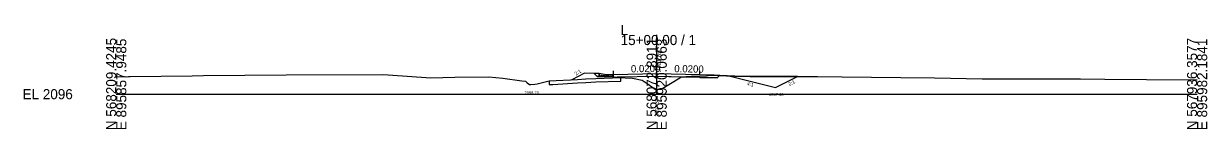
# Model space of a CAD drawing. Extents: x -26 to 1603, y -10 to 13527.
# Drawn here: x -25.7 to 302.8, y 2490.3 to 2519.2 of the extents above; entities that cross this region are included whole.
import ezdxf

# ---------------------------------------------------------------- set-up
doc = ezdxf.new("R2010")
doc.units = 0
for name, color, linetype in [('Default', 7, 'Continuous'), ('Exist XS Center Line Elevation Label', 7, 'Continuous'), ('Exist XS Ground Line', 7, 'Continuous'), ('Old_Level_61', 7, 'Continuous'), ('Old_Level_63', 7, 'Continuous'), ('Prop XS Ditch Slope Text', 7, 'Continuous'), ('Prop XS Ditch Standard Text', 7, 'Continuous'), ('Prop XS Earthwork Shape', 7, 'Continuous'), ('Prop XS EOT Tick Mark', 7, 'Continuous'), ('Prop XS Finish Grade', 7, 'Continuous'), ('Prop XS Finish Grade Earthwork', 7, 'Continuous'), ('Prop XS Finish Grade Paved Shoulder', 7, 'Continuous'), ('Prop XS Finish Grade Pavement', 7, 'Continuous'), ('Prop XS Side Slope Text', 7, 'Continuous'), ('Prop XS Subgrade Earthwork', 7, 'Continuous'), ('Prop XSC Text', 7, 'Continuous'), ('Typical Curb CELL', 7, 'Continuous')]:
    doc.layers.add(name, color=color, linetype=linetype)

msp = doc.modelspace()

# ---------------------------------------------------------------- linework, layer by layer
at = {"layer": 'Exist XS Ground Line'}
for p, q in [((0, 2504.85), (3.43, 2504.91)), ((3.43, 2504.91), (3.9, 2504.92)), ((3.9, 2504.92), (21.1, 2505.11)), ((21.1, 2505.11), (24.21, 2505.16)), ((24.21, 2505.16), (47.12, 2505.33)), ((47.12, 2505.33), (74.04, 2505.47)), ((74.04, 2505.47), (75.48, 2505.36)), ((75.48, 2505.36), (87.36, 2504.55)), ((87.36, 2504.55), (93.95, 2504.71)), ((93.95, 2504.71), (103.4, 2504.84)), ((103.4, 2504.84), (107.28, 2504.4)), ((107.28, 2504.4), (112.54, 2503.72)), ((112.54, 2503.72), (113.57, 2503.61)), ((113.57, 2503.61), (114.01, 2503.16)), ((116.82, 2502.88), (120.13, 2503.66)), ((120.13, 2503.66), (127.98, 2504.11)), ((127.98, 2504.11), (130.32, 2504.27)), ((130.32, 2504.27), (133.16, 2504.39)), ((133.16, 2504.39), (140.03, 2504.6)), ((140.03, 2504.6), (141.25, 2504.53)), ((141.25, 2504.53), (143.26, 2504.48)), ((143.26, 2504.48), (143.77, 2504.37)), ((143.77, 2504.37), (146.01, 2503.86)), ((146.01, 2503.86), (147.61, 2502.8)), ((151.21, 2501.39), (156.43, 2504.56)), ((156.43, 2504.56), (156.8, 2504.79)), ((156.8, 2504.79), (159.53, 2504.98)), ((159.53, 2504.98), (160.92, 2505.03)), ((160.92, 2505.03), (161.97, 2504.98)), ((161.97, 2504.98), (163.86, 2505.13)), ((163.86, 2505.13), (164.75, 2505.23)), ((164.75, 2505.23), (171.69, 2505.02)), ((171.69, 2505.02), (175.91, 2504.88)), ((175.91, 2504.88), (182.67, 2504.86)), ((182.67, 2504.86), (183.98, 2504.87)), ((183.98, 2504.87), (184.77, 2504.87)), ((184.77, 2504.87), (194.62, 2504.93)), ((194.62, 2504.93), (201.45, 2504.84)), ((201.45, 2504.84), (209.66, 2504.7)), ((209.66, 2504.7), (217.79, 2504.6)), ((217.79, 2504.6), (227.12, 2504.5)), ((227.12, 2504.5), (240.35, 2504.29)), ((240.35, 2504.29), (247.3, 2504.3)), ((247.3, 2504.3), (252.3, 2504.3)), ((252.3, 2504.3), (267.61, 2504.21)), ((267.61, 2504.21), (274.36, 2504.14)), ((274.36, 2504.14), (285.92, 2504.07)), ((285.92, 2504.07), (300, 2503.94)), ((114.01, 2503.16), (114.67, 2502.71)), ((114.67, 2502.71), (115.04, 2502.7)), ((115.04, 2502.7), (116.23, 2502.76)), ((116.23, 2502.76), (116.82, 2502.88)), ((147.61, 2502.8), (149.65, 2501.31)), ((149.65, 2501.31), (150.05, 2501.31)), ((150.05, 2501.31), (151.21, 2501.39))]:
    msp.add_line(p, q, dxfattribs=at)
at = {"layer": 'Old_Level_61'}
for p, q in [((120.13, 2503.66), (120.13, 2502.66)), ((133.16, 2503.39), (140.03, 2503.6)), ((140.03, 2503.6), (140.03, 2504.6)), ((120.13, 2502.66), (121.15, 2502.72)), ((121.15, 2502.72), (127.98, 2503.11)), ((127.98, 2503.11), (130.32, 2503.27)), ((130.32, 2503.27), (133.16, 2503.39))]:
    msp.add_line(p, q, dxfattribs=at)
at = {"layer": 'Old_Level_63'}
for p, q in [((150, 2500), (150, 2516.42)), ((0, 2500), (150, 2500)), ((150, 2500), (300, 2500))]:
    msp.add_line(p, q, dxfattribs=at)
at = {"layer": 'Prop XS Earthwork Shape'}
for points in [[(139, 2504.68), (138, 2504.66), (138, 2504.87), (134, 2504.87), (133.5, 2504.86), (132.63, 2505.73), (130, 2505.78), (126.48, 2504.02), (127.98, 2504.11), (130.32, 2504.27), (133.16, 2504.39), (140.03, 2504.6), (141.25, 2504.53), (143.26, 2504.48), (143.77, 2504.37), (146.01, 2503.86), (147.61, 2502.8), (149.65, 2501.31), (150.05, 2501.31), (151.21, 2501.39), (156.43, 2504.56), (156.75, 2504.76), (150, 2504.9)], [(156.75, 2504.76), (156.8, 2504.79), (159.53, 2504.98), (160.92, 2505.03), (161.97, 2504.98), (163.86, 2505.13), (164.75, 2505.23), (167.4, 2505.15), (166.81, 2504.56), (162, 2504.66)], [(167.4, 2505.15), (167.5, 2505.25), (169.53, 2505.09)], [(169.53, 2505.09), (170, 2505.05), (182.96, 2501.81), (189.13, 2504.9), (184.77, 2504.87), (183.98, 2504.87), (182.67, 2504.86), (175.91, 2504.88), (171.69, 2505.02)]]:
    msp.add_lwpolyline(points, close=True, dxfattribs=at)
at = {"layer": 'Prop XS EOT Tick Mark'}
for p, q in [((138, 2505.45), (138, 2506.45)), ((162, 2505.45), (162, 2506.45))]:
    msp.add_line(p, q, dxfattribs=at)
at = {"layer": 'Prop XS Finish Grade'}
for p, q in [((134, 2505.7), (132.63, 2505.73)), ((166, 2505.37), (167.5, 2505.25))]:
    msp.add_line(p, q, dxfattribs=at)
at = {"layer": 'Prop XS Finish Grade Earthwork'}
for p, q in [((130, 2505.78), (126.48, 2504.02)), ((132.63, 2505.73), (130, 2505.78)), ((167.5, 2505.25), (170, 2505.05)), ((170, 2505.05), (182.96, 2501.81)), ((182.96, 2501.81), (189.13, 2504.9))]:
    msp.add_line(p, q, dxfattribs=at)
at = {"layer": 'Prop XS Finish Grade Paved Shoulder'}
msp.add_line((162, 2505.45), (166, 2505.37), dxfattribs=at)
at = {"layer": 'Prop XS Finish Grade Pavement'}
for p, q in [((138, 2505.45), (150, 2505.69)), ((150, 2505.69), (162, 2505.45))]:
    msp.add_line(p, q, dxfattribs=at)
at = {"layer": 'Prop XS Subgrade Earthwork'}
for p, q in [((133.5, 2504.86), (132.63, 2505.73)), ((133.5, 2504.86), (134, 2504.87)), ((138, 2504.87), (134, 2504.87)), ((138, 2504.87), (138, 2504.66)), ((139, 2504.68), (138, 2504.66)), ((150, 2504.9), (139, 2504.68)), ((162, 2504.66), (150, 2504.9)), ((162, 2504.66), (166.81, 2504.56)), ((166.81, 2504.56), (167.5, 2505.25))]:
    msp.add_line(p, q, dxfattribs=at)
at = {"layer": 'Typical Curb CELL'}
for p, q in [((134, 2504.87), (134, 2505.7)), ((136, 2505.37), (134, 2505.7)), ((134, 2504.87), (138, 2504.87)), ((134.04, 2505.32), (134.19, 2505.37)), ((134.17, 2505.28), (134.04, 2505.32)), ((134.19, 2505.37), (134.17, 2505.28)), ((134.71, 2505.24), (134.6, 2505.16)), ((134.6, 2505.16), (134.77, 2505.12)), ((134.77, 2505.12), (134.71, 2505.24)), ((135.45, 2505.29), (135.41, 2505.18)), ((135.41, 2505.18), (135.53, 2505.17)), ((135.53, 2505.17), (135.45, 2505.29)), ((135.96, 2505.24), (135.85, 2505.16)), ((135.85, 2505.16), (136.02, 2505.12)), ((136.02, 2505.12), (135.96, 2505.24)), ((138, 2505.45), (136, 2505.37)), ((136.7, 2505.29), (136.66, 2505.18)), ((136.66, 2505.18), (136.78, 2505.17)), ((136.78, 2505.17), (136.7, 2505.29)), ((137.41, 2505.09), (137.31, 2505.02)), ((137.31, 2505.02), (137.47, 2504.98)), ((137.47, 2504.98), (137.41, 2505.09)), ((137.74, 2505.34), (137.71, 2505.22)), ((137.71, 2505.22), (137.83, 2505.22)), ((137.83, 2505.22), (137.74, 2505.34)), ((138, 2504.87), (138, 2505.45))]:
    msp.add_line(p, q, dxfattribs=at)
for centre in [(134.07, 2505.41), (134.16, 2505.13), (134.18, 2505.58), (134.25, 2505.03), (134.28, 2505.18), (134.38, 2505.55), (134.54, 2505.21), (134.56, 2505.16), (134.73, 2505.08), (134.75, 2505.48), (134.76, 2505.18), (134.95, 2504.96), (134.96, 2505.14), (135, 2505.26), (135.11, 2505.42), (135.13, 2505.23), (135.16, 2505.1), (135.22, 2505.13), (135.27, 2505), (135.41, 2505.13), (135.53, 2505.18), (135.57, 2505.33), (135.63, 2505.18), (135.63, 2504.97), (135.72, 2505.13), (135.78, 2505.27), (135.79, 2505.21), (135.81, 2505.16), (135.98, 2505.06), (136.01, 2505.18), (136.09, 2504.98), (136.21, 2505.14), (136.25, 2505.26), (136.3, 2505.22), (136.32, 2504.95), (136.38, 2505.23), (136.41, 2505.1), (136.47, 2505.13), (136.53, 2505.31), (136.64, 2504.96), (136.89, 2505.39), (136.93, 2505.26), (137.13, 2505.03), (137.28, 2505.31), (137.5, 2505.32), (137.57, 2505.09), (137.74, 2504.95), (137.86, 2505.11), (137.9, 2505.35)]:
    msp.add_circle(centre, 0.00802, dxfattribs=at)

# ---------------------------------------------------------------- texts
at = {"layer": 'Default'}
for rotation, p in [(1.1458, (142.87, 2506.04)), (358.8542, (154.87, 2506.1))]:
    msp.add_text('0.0200', height=2, rotation=rotation, dxfattribs=at).set_placement(p)
at = {"layer": 'Exist XS Center Line Elevation Label'}
msp.add_text('2097.31', height=1, rotation=90, dxfattribs=at).set_placement((150.5, 2493.78))
at = {"layer": 'Old_Level_63'}
for s, p in [('15+00.00 / 1', (140, 2513.62)), ('L', (140, 2516.42)), ('EL 2096', (-26, 2498.6))]:
    msp.add_text(s, height=2.8, dxfattribs=at).set_placement(p)
for s, p in [('N 568209.4245', (0, 2490)), ('E 895857.9485', (2.8, 2490)), ('N 568072.8911', (150, 2490)), ('E 895920.0663', (152.8, 2490)), ('N 567936.3577', (300, 2490)), ('E 895982.1841', (302.8, 2490))]:
    msp.add_text(s, height=2.8, rotation=90, dxfattribs=at).set_placement(p)
at = {"layer": 'Prop XS Ditch Slope Text'}
for s, rotation, p in [('2:1', 32.2598, (127.58, 2505.11)), ('4:1', 345.9638, (174.97, 2502.52))]:
    msp.add_text(s, height=1, rotation=rotation, dxfattribs=at).set_placement(p)
at = {"layer": 'Prop XS Ditch Standard Text'}
for s, p in [('2098.70', (113.32, 2499.98)), ('2097.80', (181.23, 2499.47))]:
    msp.add_text(s, height=0.8, dxfattribs=at).set_placement(p)
at = {"layer": 'Prop XS Side Slope Text'}
msp.add_text('2:1', height=1, rotation=26.5651, dxfattribs=at).set_placement((186.82, 2502.26))
at = {"layer": 'Prop XSC Text'}
msp.add_text(' 2101.69', height=1.2, rotation=90, dxfattribs=at).set_placement((151.2, 2505.69))

doc.saveas('drawing.dxf')
